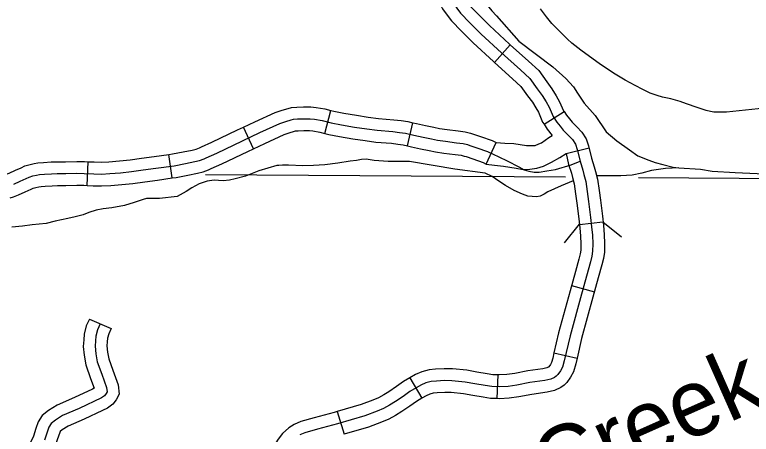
# Model space of a CAD drawing. Extents: x 670147 to 673275, y 705573 to 707613.
# Drawn here: x 672042.9 to 672136.1, y 706503.8 to 706556.9 of the extents above; entities that cross this region are included whole.
import ezdxf

# ---------------------------------------------------------------- set-up
doc = ezdxf.new("R2010")
doc.units = 0
for name, color, linetype in [('32', 7, 'Continuous'), ('35', 7, 'Continuous'), ('38', 7, 'Continuous'), ('45', 7, 'Continuous'), ('5', 7, 'Continuous')]:
    doc.layers.add(name, color=color, linetype=linetype)

msp = doc.modelspace()

# ---------------------------------------------------------------- linework, layer by layer
at = {"layer": '32'}
for p, q in [((672103.554, 706550.825), (672105.561, 706553.054)), ((672082.114, 706541.848), (672082.837, 706544.759)), ((672109.838, 706543.011), (672112.371, 706544.618)), ((672073.075, 706539.919), (672071.806, 706542.638)), ((672092.58, 706540.272), (672093.236, 706543.2)), ((672102.503, 706537.982), (672103.793, 706540.691)), ((672062.785, 706536.221), (672062.369, 706539.192)), ((672052.009, 706535.281), (672052.149, 706538.277)), ((672114.312, 706530.356), (672117.295, 706530.675)), ((672113.328, 706522.641), (672116.22, 706521.845)), ((672111.089, 706514.127), (672114.013, 706513.455)), ((672092.841, 706510.94), (672094.381, 706508.366)), ((672103.97, 706511.327), (672103.883, 706508.329)), ((672083.679, 706506.699), (672084.524, 706503.82))]:
    msp.add_line(p, q, dxfattribs=at)
for points in [[(672098.653, 706560.585), (672098.946, 706560.301), (672100.039, 706558.52), (672100.41, 706558.04), (672101.527, 706556.87), (672102.936, 706555.488), (672105.457, 706553.148), (672105.561, 706553.054)], [(672096.568, 706558.428), (672096.988, 706557.621), (672097.587, 706556.787), (672098.132, 706556.082), (672099.39, 706554.763), (672100.865, 706553.317), (672103.433, 706550.934), (672103.554, 706550.825)], [(672098.551, 706558.779), (672098.451, 706558.446), (672098.465, 706558.136), (672098.79, 706557.683), (672099.271, 706557.061), (672100.458, 706555.816), (672101.9, 706554.402), (672104.445, 706552.041), (672106.848, 706549.877), (672108.035, 706548.789), (672108.968, 706547.502), (672109.604, 706546.639), (672110.099, 706545.861), (672110.467, 706545.183), (672110.99, 706543.995), (672111.456, 706543.26), (672111.88, 706542.75), (672112.262, 706542.27), (672112.898, 706541.648), (672113.421, 706541.096), (672113.803, 706540.488), (672114.043, 706539.837), (672114.397, 706538.339)], [(672137.73, 706545.057), (672132.916, 706544.54), (672131.748, 706544.527), (672131.305, 706544.54), (672130.889, 706544.608), (672130.338, 706544.755), (672129.197, 706545.145), (672127.855, 706545.588), (672127.062, 706545.87), (672125.894, 706546.206), (672124.847, 706546.434), (672124.149, 706546.636), (672123.276, 706546.945), (672122.323, 706547.388), (672121.356, 706547.898), (672120.108, 706548.57), (672118.845, 706549.362), (672116.979, 706550.571), (672114.495, 706552.357), (672113.367, 706553.257), (672112.79, 706553.754), (672110.843, 706555.728), (672110.145, 706556.588), (672109.393, 706557.595)], [(672105.561, 706553.054), (672107.857, 706550.988), (672109.161, 706549.792), (672110.179, 706548.387), (672110.842, 706547.488), (672111.393, 706546.622), (672111.815, 706545.843), (672112.317, 706544.703), (672112.371, 706544.618)], [(672103.554, 706550.825), (672105.839, 706548.767), (672106.91, 706547.785), (672107.758, 706546.616), (672108.367, 706545.79), (672108.805, 706545.101), (672109.119, 706544.522), (672109.663, 706543.287), (672109.838, 706543.011)], [(672071.806, 706542.638), (672073.251, 706543.312), (672075.821, 706544.484), (672076.685, 706544.794), (672077.441, 706545.01), (672077.867, 706545.134), (672078.567, 706545.18), (672079.384, 706545.216), (672080.32, 706545.203), (672080.992, 706545.135), (672082.081, 706544.947), (672082.837, 706544.759)], [(672082.837, 706544.759), (672083.232, 706544.661), (672084.491, 706544.422), (672086.107, 706544.143), (672087.602, 706543.911), (672088.882, 706543.748), (672090.846, 706543.589), (672091.77, 706543.469), (672092.584, 706543.346), (672093.236, 706543.2)], [(672112.371, 706544.618), (672112.671, 706544.145), (672113.044, 706543.697), (672113.378, 706543.276), (672113.967, 706542.7), (672114.612, 706542.02), (672115.156, 706541.154), (672115.482, 706540.271), (672115.844, 706538.737), (672116.194, 706537.63), (672116.345, 706537.025), (672116.59, 706536.077), (672116.798, 706534.642)], [(672056.249, 706536.89), (672057.63, 706537.026), (672059.112, 706537.23), (672060.708, 706537.445), (672063.05, 706537.773), (672064.453, 706538.033), (672065.641, 706538.282), (672066.252, 706538.441), (672066.807, 706538.645), (672067.09, 706538.769), (672068.414, 706539.369), (672071.695, 706540.931), (672073.879, 706541.95), (672076.386, 706543.093), (672077.145, 706543.365), (672077.857, 706543.569), (672078.129, 706543.648), (672078.65, 706543.682), (672079.408, 706543.716), (672080.234, 706543.704), (672080.788, 706543.648), (672081.773, 706543.478), (672082.911, 706543.195), (672084.224, 706542.946), (672085.864, 706542.663), (672087.392, 706542.425), (672088.727, 706542.256), (672090.689, 706542.097), (672091.56, 706541.984), (672092.307, 706541.871), (672093.369, 706541.633), (672094.534, 706541.384), (672095.587, 706541.158), (672096.345, 706541.01), (672097.352, 706540.852), (672098.766, 706540.671), (672099.604, 706540.569), (672100.135, 706540.444), (672100.459, 706540.343), (672101.319, 706540.048), (672102.699, 706539.55), (672104.125, 706538.871), (672105.166, 706538.396), (672106.66, 706537.626), (672107.339, 706537.264), (672107.905, 706537.083), (672108.584, 706536.969), (672109.217, 706536.969), (672110.19, 706537.128), (672111.299, 706537.309), (672113.291, 706537.898), (672114.397, 706538.339)], [(672062.369, 706539.192), (672062.809, 706539.254), (672064.162, 706539.505), (672065.299, 706539.743), (672065.804, 706539.874), (672066.245, 706540.036), (672066.478, 706540.139), (672067.782, 706540.73), (672071.056, 706542.288), (672071.806, 706542.638)], [(672093.236, 706543.2), (672093.689, 706543.098), (672094.849, 706542.851), (672095.887, 706542.627), (672096.604, 706542.488), (672097.564, 706542.337), (672098.952, 706542.159), (672099.866, 706542.048), (672100.532, 706541.892), (672100.927, 706541.768), (672101.816, 706541.463), (672103.278, 706540.936), (672103.793, 706540.691)], [(672109.838, 706543.011), (672110.242, 706542.374), (672110.887, 706541.599)], [(672073.075, 706539.919), (672074.507, 706540.588), (672076.952, 706541.702), (672077.604, 706541.936), (672078.274, 706542.127), (672078.391, 706542.162), (672078.732, 706542.184), (672079.431, 706542.215), (672080.147, 706542.205), (672080.584, 706542.161), (672081.464, 706542.009), (672082.114, 706541.848)], [(672082.113, 706541.848), (672082.59, 706541.729), (672083.956, 706541.47), (672085.621, 706541.183), (672087.182, 706540.94), (672088.572, 706540.763), (672090.532, 706540.605), (672091.351, 706540.498), (672092.031, 706540.395), (672092.58, 706540.272)], [(672103.793, 706540.691), (672104.861, 706540.62), (672106.028, 706540.561), (672107.6, 706540.31), (672108.386, 706540.321), (672108.735, 706540.344), (672109.166, 706540.527), (672109.527, 706540.67), (672110.435, 706541.328), (672110.887, 706541.599)], [(672062.785, 706536.221), (672063.291, 706536.292), (672064.744, 706536.562), (672065.984, 706536.822), (672066.7, 706537.007), (672067.368, 706537.253), (672067.701, 706537.4), (672069.045, 706538.009), (672072.334, 706539.574), (672073.075, 706539.919)], [(672092.58, 706540.272), (672093.048, 706540.168), (672094.22, 706539.917), (672095.286, 706539.688), (672096.085, 706539.533), (672097.14, 706539.367), (672098.58, 706539.182), (672099.341, 706539.09), (672099.739, 706538.997), (672099.991, 706538.917), (672100.822, 706538.633), (672102.121, 706538.164), (672102.503, 706537.982)], [(672102.503, 706537.982), (672103.589, 706537.843), (672104.703, 706537.719), (672106.316, 706537.46), (672107.197, 706537.307), (672108.036, 706537.313), (672108.946, 706537.452), (672109.781, 706537.726), (672110.765, 706538.236), (672111.846, 706538.798), (672112.621, 706539.333), (672115.541, 706540.022)], [(672052.149, 706538.277), (672052.911, 706538.242), (672053.814, 706538.21), (672054.783, 706538.262), (672056.107, 706538.383), (672057.454, 706538.516), (672058.91, 706538.716), (672060.503, 706538.931), (672062.369, 706539.192)], [(672112.621, 706539.333), (672112.95, 706537.94), (672113.306, 706536.813), (672113.438, 706536.286), (672113.645, 706535.485), (672113.828, 706534.214)], [(672041.359, 706536.55), (672041.692, 706536.655), (672042.168, 706536.836), (672042.933, 706537.191), (672043.665, 706537.518), (672044.15, 706537.746), (672044.814, 706537.932), (672045.318, 706538.031), (672045.769, 706538.127), (672046.509, 706538.194), (672047.448, 706538.242), (672048.202, 706538.265), (672049.276, 706538.277), (672050.706, 706538.323), (672051.693, 706538.299), (672052.149, 706538.277)], [(672114.397, 706538.339), (672114.75, 706537.221), (672114.891, 706536.656), (672115.118, 706535.781), (672115.485, 706533.236), (672115.725, 706531.242), (672115.853, 706530.054), (672115.952, 706528.98), (672115.994, 706527.905), (672115.98, 706526.983), (672115.881, 706526.347), (672115.697, 706525.597), (672114.58, 706521.539), (672113.124, 706516.283), (672112.389, 706513.087), (672112.177, 706512.309), (672111.909, 706511.843), (672111.569, 706511.362), (672111.381, 706511.18), (672111.159, 706511.008), (672110.679, 706510.782), (672109.958, 706510.627), (672108.05, 706510.344), (672106.396, 706510.018), (672105.279, 706509.877), (672104.19, 706509.82), (672103.215, 706509.849), (672102.381, 706509.976), (672101.066, 706510.202), (672099.844, 706510.414), (672098.176, 706510.584), (672097.243, 706510.598), (672096.211, 706510.542), (672095.56, 706510.485), (672094.882, 706510.301), (672094.246, 706510.033), (672092.875, 706509.212), (672092.012, 706508.604), (672091.023, 706507.94), (672090.302, 706507.501), (672089.538, 706507.091), (672088.719, 706506.724), (672087.164, 706506.158), (672083.695, 706505.14), (672081.164, 706504.447), (672079.567, 706504.009), (672078.917, 706503.74)], [(672042.751, 706535.453), (672043.554, 706535.826), (672044.29, 706536.154), (672044.675, 706536.336), (672045.161, 706536.471), (672045.62, 706536.562), (672045.993, 706536.641), (672046.615, 706536.698), (672047.509, 706536.743), (672048.233, 706536.766), (672049.308, 706536.777), (672050.712, 706536.822), (672051.639, 706536.8), (672052.85, 706536.743), (672053.828, 706536.709), (672054.891, 706536.766), (672056.249, 706536.89)], [(672052.009, 706535.281), (672052.789, 706535.244), (672053.842, 706535.208), (672055, 706535.269), (672056.391, 706535.397), (672057.805, 706535.536), (672059.314, 706535.743), (672060.912, 706535.959), (672062.785, 706536.221)], [(672042.263, 706533.689), (672042.678, 706533.82), (672043.335, 706534.07), (672044.176, 706534.461), (672044.915, 706534.791), (672045.199, 706534.925), (672045.509, 706535.011), (672045.921, 706535.092), (672046.217, 706535.155), (672046.721, 706535.201), (672047.571, 706535.244), (672048.265, 706535.266), (672049.34, 706535.277), (672050.717, 706535.322), (672051.586, 706535.3), (672052.009, 706535.281)], [(672113.828, 706534.214), (672113.998, 706533.039), (672114.235, 706531.072), (672114.36, 706529.906), (672114.454, 706528.881), (672114.493, 706527.887), (672114.482, 706527.11), (672114.409, 706526.641), (672114.245, 706525.975), (672113.81, 706524.394)], [(672116.798, 706534.642), (672116.972, 706533.433), (672117.216, 706531.412), (672117.345, 706530.203), (672117.449, 706529.078), (672117.494, 706527.923), (672117.478, 706526.856), (672117.353, 706526.052), (672117.149, 706525.219), (672116.703, 706523.598)], [(672113.81, 706524.394), (672113.134, 706521.938), (672111.67, 706516.651), (672111.089, 706514.127)], [(672116.703, 706523.598), (672116.026, 706521.14), (672114.579, 706515.914), (672114.013, 706513.455)], [(672111.089, 706514.127), (672110.934, 706513.453), (672110.781, 706512.89), (672110.643, 706512.651), (672110.425, 706512.342), (672110.398, 706512.316), (672110.372, 706512.295), (672110.195, 706512.212), (672109.689, 706512.103), (672107.795, 706511.822), (672106.156, 706511.5), (672105.146, 706511.372), (672104.173, 706511.322), (672103.97, 706511.327)], [(672114.013, 706513.455), (672113.844, 706512.721), (672113.574, 706511.728), (672113.174, 706511.034), (672112.714, 706510.382), (672112.364, 706510.044), (672111.947, 706509.721), (672111.163, 706509.352), (672110.226, 706509.15), (672108.304, 706508.865), (672106.635, 706508.537), (672105.412, 706508.382), (672104.208, 706508.319), (672103.884, 706508.329)], [(672103.97, 706511.327), (672103.35, 706511.345), (672102.621, 706511.457), (672101.322, 706511.68), (672100.048, 706511.901), (672098.263, 706512.083), (672097.213, 706512.099), (672096.105, 706512.038), (672095.297, 706511.968), (672094.392, 706511.723), (672093.566, 706511.374), (672092.841, 706510.94)], [(672092.841, 706510.94), (672092.056, 706510.471), (672091.162, 706509.84), (672090.215, 706509.204), (672089.557, 706508.804), (672088.876, 706508.438), (672088.155, 706508.115), (672086.696, 706507.584), (672083.679, 706506.699)], [(672103.883, 706508.329), (672103.08, 706508.352), (672102.141, 706508.495), (672100.811, 706508.724), (672099.639, 706508.927), (672098.088, 706509.085), (672097.272, 706509.098), (672096.317, 706509.045), (672095.824, 706509.002), (672095.372, 706508.88), (672094.926, 706508.692), (672094.381, 706508.366)], [(672094.381, 706508.366), (672093.693, 706507.954), (672092.863, 706507.369), (672091.831, 706506.676), (672091.047, 706506.199), (672090.201, 706505.745), (672089.283, 706505.333), (672087.632, 706504.732), (672084.524, 706503.82)], [(672083.679, 706506.699), (672083.285, 706506.583), (672080.768, 706505.894), (672079.08, 706505.431), (672078.218, 706505.074), (672077.553, 706504.645), (672076.759, 706503.905), (672076.189, 706503.206), (672075.615, 706502.254), (672075.177, 706501.126), (672074.823, 706499.916)]]:
    msp.add_lwpolyline(points, dxfattribs=at)
at = {"layer": '35'}
for points in [[(672097.005, 706565.429), (672098.751, 706563.535), (672100.122, 706562.019), (672100.744, 706560.711), (672101.275, 706559.801), (672102.297, 706558.478), (672103.211, 706557.365), (672103.802, 706556.734), (672106.636, 706553.494), (672110.95, 706550.278), (672112.615, 706548.8), (672113.582, 706547.729), (672114.091, 706546.938)], [(672114.091, 706546.938), (672114.933, 706545.675), (672116.316, 706544.112), (672117.697, 706542.041), (672119.056, 706540.903), (672120.664, 706539.775), (672121.688, 706539.038), (672123.079, 706538.465), (672123.899, 706538.191), (672124.874, 706537.93), (672126.169, 706537.603), (672126.904, 706537.518)], [(672092.796, 706538.297), (672091.73, 706538.297), (672090.132, 706538.283), (672088.351, 706538.438), (672087.347, 706538.58), (672086.74, 706538.537), (672086.089, 706538.438), (672085.298, 706538.353), (672083.736, 706538.085), (672082.096, 706537.901), (672080.668, 706537.788), (672079.325, 706537.76), (672077.488, 706537.83), (672076.724, 706537.844), (672076.286, 706537.802), (672076.031, 706537.776)], [(672113.543, 706535.863), (672111.997, 706535.227), (672110.335, 706534.474), (672109.854, 706534.191), (672109.345, 706533.937), (672108.865, 706533.852), (672107.801, 706533.909), (672107.123, 706534.163), (672106.049, 706534.644), (672104.974, 706535.266), (672104.126, 706535.832), (672103.278, 706536.426), (672102.373, 706536.822), (672098.528, 706537.331), (672092.796, 706538.297)], [(672076.031, 706537.776), (672073.743, 706537.109), (672072.04, 706536.436), (672070.767, 706536.111), (672070.032, 706535.956), (672069.241, 706535.857), (672068.647, 706535.899), (672068.096, 706535.927), (672067.191, 706535.814), (672066.215, 706535.475), (672065.268, 706534.952), (672064.562, 706534.527), (672063.431, 706533.877), (672061.187, 706533.639), (672059.514, 706533.641)], [(672126.904, 706537.518), (672125.191, 706537.406), (672123.438, 706537.152), (672122.194, 706536.84), (672120.978, 706536.558), (672119.536, 706536.473), (672116.488, 706536.473)], [(672126.904, 706537.518), (672129.641, 706537.342), (672131.096, 706537.077), (672134.034, 706536.891), (672139.575, 706536.668), (672145.004, 706536.519), (672148.648, 706536.296), (672152.558, 706535.798), (672155.212, 706535.391), (672157.866, 706535.214), (672160.856, 706535.161)], [(672059.514, 706533.641), (672059.119, 706533.489), (672057.974, 706533.107), (672056.73, 706532.754), (672055.133, 706532.443), (672054.059, 706532.33), (672053.14, 706532.16), (672052.238, 706531.85), (672051.531, 706531.567), (672050.513, 706531.299), (672049.566, 706531.086), (672047.979, 706530.747), (672046.834, 706530.45), (672045.081, 706530.28), (672043.851, 706530.139), (672042.494, 706530.012)]]:
    msp.add_lwpolyline(points, dxfattribs=at)
at = {"layer": '38'}
for points in [[(672117.295, 706530.672), (672119.625, 706528.782)], [(672112.422, 706528.029), (672114.311, 706530.36)]]:
    msp.add_lwpolyline(points, dxfattribs=at)
at = {"layer": '45'}
msp.add_line((672052.3, 706518.388), (672055.045, 706517.179), dxfattribs=at)
for points in [[(672052.3, 706518.388), (672051.912, 706517.508), (672051.643, 706516.464), (672051.579, 706515.756), (672051.515, 706514.93), (672051.639, 706513.8), (672051.837, 706512.594), (672052.458, 706510.887), (672052.915, 706509.632), (672052.69, 706509.526)], [(672053.672, 706517.783), (672053.334, 706517.015), (672053.126, 706516.208), (672053.074, 706515.631), (672053.022, 706514.954), (672053.126, 706514.004), (672053.295, 706512.975), (672053.868, 706511.4), (672054.479, 706509.72), (672054.544, 706509.186), (672054.427, 706508.965), (672054.219, 706508.691), (672053.829, 706508.405), (672051.017, 706507.077), (672048.909, 706506.179), (672047.998, 706505.606), (672047.477, 706505.176), (672047.191, 706504.72), (672046.956, 706504.082), (672046.631, 706503.054)], [(672055.045, 706517.179), (672054.756, 706516.522), (672054.609, 706515.951), (672054.568, 706515.506), (672054.528, 706514.978), (672054.612, 706514.207), (672054.752, 706513.356), (672055.277, 706511.912), (672055.948, 706510.072), (672056.09, 706508.901), (672055.695, 706508.154), (672055.281, 706507.61), (672054.6, 706507.11), (672053.972, 706506.814)], [(672052.69, 706509.526), (672050.403, 706508.446), (672048.211, 706507.512), (672047.117, 706506.824), (672046.336, 706506.179), (672045.837, 706505.385), (672045.536, 706504.567), (672045.229, 706503.596), (672045.016, 706503.133), (672044.66, 706502.408), (672044.567, 706502.219)], [(672053.972, 706506.814), (672051.632, 706505.708), (672049.606, 706504.845), (672048.878, 706504.387), (672048.618, 706504.173), (672048.544, 706504.055), (672048.376, 706503.597), (672048.033, 706502.512), (672047.725, 706501.844), (672047.352, 706501.085), (672047.258, 706500.894)]]:
    msp.add_lwpolyline(points, dxfattribs=at)
at = {"layer": '5'}
for points in [[(672112.539, 706536.303), (672067.012, 706536.608)], [(672147.28, 706536.069), (672121.772, 706536.24)]]:
    msp.add_lwpolyline(points, dxfattribs=at)

# ---------------------------------------------------------------- texts
at = {"layer": '35'}
msp.add_text('Creek', height=8.448, rotation=23.93548, dxfattribs=at).set_placement((672110.814, 706495.304))

doc.saveas('drawing.dxf')
